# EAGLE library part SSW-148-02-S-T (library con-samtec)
THROUGH-HOLE .025" SQ POST SOCKET Source: Samtec SSW.pdf
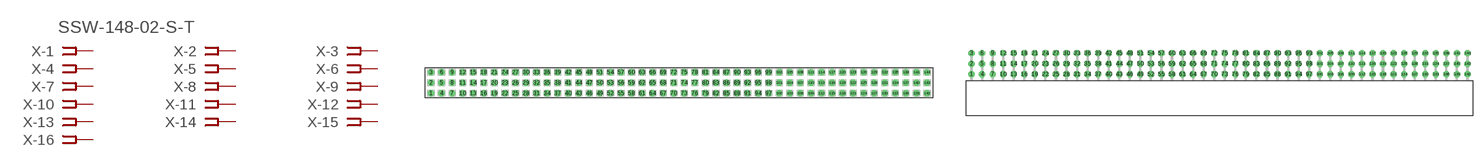
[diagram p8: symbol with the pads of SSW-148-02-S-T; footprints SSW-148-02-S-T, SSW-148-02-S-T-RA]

Designator prefix X; gates -1=FPINV -2=FPIN -3=FPIN -4=FPIN -5=FPIN -6=FPIN -7=FPIN -8=FPIN -9=FPIN -10=FPIN -11=FPIN -12=FPIN -13=FPIN -14=FPIN -15=FPIN -16=FPIN -17=FPIN -18=FPIN -19=FPIN -20=FPIN -21=FPIN -22=FPIN -23=FPIN -24=FPIN -25=FPIN -26=FPIN -27=FPIN -28=FPIN -29=FPIN -30=FPIN -31=FPIN -32=FPIN -33=FPIN -34=FPIN -35=FPIN -36=FPIN -37=FPIN -38=FPIN -39=FPIN -40=FPIN -41=FPIN -42=FPIN -43=FPIN -44=FPIN -45=FPIN -46=FPIN -47=FPIN -48=FPIN -49=FPIN -50=FPIN -51=FPIN -52=FPIN -53=FPIN -54=FPIN -55=FPIN -56=FPIN -57=FPIN -58=FPIN -59=FPIN -60=FPIN -61=FPIN -62=FPIN -63=FPIN -64=FPIN -65=FPIN -66=FPIN -67=FPIN -68=FPIN -69=FPIN -70=FPIN -71=FPIN -72=FPIN -73=FPIN -74=FPIN -75=FPIN -76=FPIN -77=FPIN -78=FPIN -79=FPIN -80=FPIN -81=FPIN -82=FPIN -83=FPIN -84=FPIN -85=FPIN -86=FPIN -87=FPIN -88=FPIN -89=FPIN -90=FPIN -91=FPIN -92=FPIN -93=FPIN -94=FPIN -95=FPIN -96=FPIN -97=FPIN -98=FPIN -99=FPIN -100=FPIN -101=FPIN -102=FPIN -103=FPIN -104=FPIN -105=FPIN -106=FPIN -107=FPIN -108=FPIN -109=FPIN -110=FPIN -111=FPIN -112=FPIN -113=FPIN -114=FPIN -115=FPIN -116=FPIN -117=FPIN -118=FPIN -119=FPIN -120=FPIN -121=FPIN -122=FPIN -123=FPIN -124=FPIN -125=FPIN -126=FPIN -127=FPIN -128=FPIN -129=FPIN -130=FPIN -131=FPIN -132=FPIN -133=FPIN -134=FPIN -135=FPIN -136=FPIN -137=FPIN -138=FPIN -139=FPIN -140=FPIN -141=FPIN -142=FPIN -143=FPIN -144=FPIN

## SSW-148-02-S-T (OC_FARNELL: unknown; OC_NEWARK: unknown)  [SSW-148-02-S-T]
1  -1:1  pas
2  -2:1  pas
3  -3:1  pas
4  -4:1  pas
5  -5:1  pas
6  -6:1  pas
7  -7:1  pas
8  -8:1  pas
9  -9:1  pas
10  -10:1  pas
11  -11:1  pas
12  -12:1  pas
13  -13:1  pas
14  -14:1  pas
15  -15:1  pas
16  -16:1  pas
17  -17:1  pas
18  -18:1  pas
19  -19:1  pas
20  -20:1  pas
21  -21:1  pas
22  -22:1  pas
23  -23:1  pas
24  -24:1  pas
25  -25:1  pas
26  -26:1  pas
27  -27:1  pas
28  -28:1  pas
29  -29:1  pas
30  -30:1  pas
31  -31:1  pas
32  -32:1  pas
33  -33:1  pas
34  -34:1  pas
35  -35:1  pas
36  -36:1  pas
37  -37:1  pas
38  -38:1  pas
39  -39:1  pas
40  -40:1  pas
41  -41:1  pas
42  -42:1  pas
43  -43:1  pas
44  -44:1  pas
45  -45:1  pas
46  -46:1  pas
47  -47:1  pas
48  -48:1  pas
49  -49:1  pas
50  -50:1  pas
51  -51:1  pas
52  -52:1  pas
53  -53:1  pas
54  -54:1  pas
55  -55:1  pas
56  -56:1  pas
57  -57:1  pas
58  -58:1  pas
59  -59:1  pas
60  -60:1  pas
61  -61:1  pas
62  -62:1  pas
63  -63:1  pas
64  -64:1  pas
65  -65:1  pas
66  -66:1  pas
67  -67:1  pas
68  -68:1  pas
69  -69:1  pas
70  -70:1  pas
71  -71:1  pas
72  -72:1  pas
73  -73:1  pas
74  -74:1  pas
75  -75:1  pas
76  -76:1  pas
77  -77:1  pas
78  -78:1  pas
79  -79:1  pas
80  -80:1  pas
81  -81:1  pas
82  -82:1  pas
83  -83:1  pas
84  -84:1  pas
85  -85:1  pas
86  -86:1  pas
87  -87:1  pas
88  -88:1  pas
89  -89:1  pas
90  -90:1  pas
91  -91:1  pas
92  -92:1  pas
93  -93:1  pas
94  -94:1  pas
95  -95:1  pas
96  -96:1  pas
97  -97:1  pas
98  -98:1  pas
99  -99:1  pas
100  -100:1  pas
101  -101:1  pas
102  -102:1  pas
103  -103:1  pas
104  -104:1  pas
105  -105:1  pas
106  -106:1  pas
107  -107:1  pas
108  -108:1  pas
109  -109:1  pas
110  -110:1  pas
111  -111:1  pas
112  -112:1  pas
113  -113:1  pas
114  -114:1  pas
115  -115:1  pas
116  -116:1  pas
117  -117:1  pas
118  -118:1  pas
119  -119:1  pas
120  -120:1  pas
121  -121:1  pas
122  -122:1  pas
123  -123:1  pas
124  -124:1  pas
125  -125:1  pas
126  -126:1  pas
127  -127:1  pas
128  -128:1  pas
129  -129:1  pas
130  -130:1  pas
131  -131:1  pas
132  -132:1  pas
133  -133:1  pas
134  -134:1  pas
135  -135:1  pas
136  -136:1  pas
137  -137:1  pas
138  -138:1  pas
139  -139:1  pas
140  -140:1  pas
141  -141:1  pas
142  -142:1  pas
143  -143:1  pas
144  -144:1  pas

## SSW-148-02-S-TRA (OC_FARNELL: unknown; OC_NEWARK: unknown)  [SSW-148-02-S-T-RA]
Pads as for SSW-148-02-S-T

## Footprint SSW-148-02-S-T (pad centres in mm)
THROUGH-HOLE .025" SQ POST SOCKET Source: Samtec SSW.pdf
drill 1 pad 1.5 octagon: 1 -59.69,-2.54; 2 -59.69,0; 3 -59.69,2.54; 4 -57.15,-2.54; 5 -57.15,0; 6 -57.15,2.54; 7 -54.61,-2.54; 8 -54.61,0; 9 -54.61,2.54; 10 -52.07,-2.54; 11 -52.07,0; 12 -52.07,2.54; 13 -49.53,-2.54; 14 -49.53,0; 15 -49.53,2.54; 16 -46.99,-2.54; 17 -46.99,0; 18 -46.99,2.54; 19 -44.45,-2.54; 20 -44.45,0; 21 -44.45,2.54; 22 -41.91,-2.54; 23 -41.91,0; 24 -41.91,2.54; 25 -39.37,-2.54; 26 -39.37,0; 27 -39.37,2.54; 28 -36.83,-2.54; 29 -36.83,0; 30 -36.83,2.54; 31 -34.29,-2.54; 32 -34.29,0; 33 -34.29,2.54; 34 -31.75,-2.54; 35 -31.75,0; 36 -31.75,2.54; 37 -29.21,-2.54; 38 -29.21,0; 39 -29.21,2.54; 40 -26.67,-2.54; 41 -26.67,0; 42 -26.67,2.54; 43 -24.13,-2.54; 44 -24.13,0; 45 -24.13,2.54; 46 -21.59,-2.54; 47 -21.59,0; 48 -21.59,2.54; 49 -19.05,-2.54; 50 -19.05,0; 51 -19.05,2.54; 52 -16.51,-2.54; 53 -16.51,0; 54 -16.51,2.54; 55 -13.97,-2.54; 56 -13.97,0; 57 -13.97,2.54; 58 -11.43,-2.54; 59 -11.43,0; 60 -11.43,2.54; 61 -8.89,-2.54; 62 -8.89,0; 63 -8.89,2.54; 64 -6.35,-2.54; 65 -6.35,0; 66 -6.35,2.54; 67 -3.81,-2.54; 68 -3.81,0; 69 -3.81,2.54; 70 -1.27,-2.54; 71 -1.27,0; 72 -1.27,2.54; 73 1.27,-2.54; 74 1.27,0; 75 1.27,2.54; 76 3.81,-2.54; 77 3.81,0; 78 3.81,2.54; 79 6.35,-2.54; 80 6.35,0; 81 6.35,2.54; 82 8.89,-2.54; 83 8.89,0; 84 8.89,2.54; 85 11.43,-2.54; 86 11.43,0; 87 11.43,2.54; 88 13.97,-2.54; 89 13.97,0; 90 13.97,2.54; 91 16.51,-2.54; 92 16.51,0; 93 16.51,2.54; 94 19.05,-2.54; 95 19.05,0; 96 19.05,2.54; 97 21.59,-2.54; 98 21.59,0; 99 21.59,2.54; 100 24.13,-2.54; 101 24.13,0; 102 24.13,2.54; 103 26.67,-2.54; 104 26.67,0; 105 26.67,2.54; 106 29.21,-2.54; 107 29.21,0; 108 29.21,2.54; 109 31.75,-2.54; 110 31.75,0; 111 31.75,2.54; 112 34.29,-2.54; 113 34.29,0; 114 34.29,2.54; 115 36.83,-2.54; 116 36.83,0; 117 36.83,2.54; 118 39.37,-2.54; 119 39.37,0; 120 39.37,2.54; 121 41.91,-2.54; 122 41.91,0; 123 41.91,2.54; 124 44.45,-2.54; 125 44.45,0; 126 44.45,2.54; 127 46.99,-2.54; 128 46.99,0; 129 46.99,2.54; 130 49.53,-2.54; 131 49.53,0; 132 49.53,2.54; 133 52.07,-2.54; 134 52.07,0; 135 52.07,2.54; 136 54.61,-2.54; 137 54.61,0; 138 54.61,2.54; 139 57.15,-2.54; 140 57.15,0; 141 57.15,2.54; 142 59.69,-2.54; 143 59.69,0; 144 59.69,2.54

## Footprint SSW-148-02-S-T-RA (pad centres in mm)
THROUGH-HOLE .025" SQ POST SOCKET Source: Samtec SSW.pdf
drill 1 pad 1.5 octagon: 1 -59.69,1.524; 2 -59.69,4.064; 3 -59.69,6.604; 4 -57.15,1.524; 5 -57.15,4.064; 6 -57.15,6.604; 7 -54.61,1.524; 8 -54.61,4.064; 9 -54.61,6.604; 10 -52.07,1.524; 11 -52.07,4.064; 12 -52.07,6.604; 13 -49.53,1.524; 14 -49.53,4.064; 15 -49.53,6.604; 16 -46.99,1.524; 17 -46.99,4.064; 18 -46.99,6.604; 19 -44.45,1.524; 20 -44.45,4.064; 21 -44.45,6.604; 22 -41.91,1.524; 23 -41.91,4.064; 24 -41.91,6.604; 25 -39.37,1.524; 26 -39.37,4.064; 27 -39.37,6.604; 28 -36.83,1.524; 29 -36.83,4.064; 30 -36.83,6.604; 31 -34.29,1.524; 32 -34.29,4.064; 33 -34.29,6.604; 34 -31.75,1.524; 35 -31.75,4.064; 36 -31.75,6.604; 37 -29.21,1.524; 38 -29.21,4.064; 39 -29.21,6.604; 40 -26.67,1.524; 41 -26.67,4.064; 42 -26.67,6.604; 43 -24.13,1.524; 44 -24.13,4.064; 45 -24.13,6.604; 46 -21.59,1.524; 47 -21.59,4.064; 48 -21.59,6.604; 49 -19.05,1.524; 50 -19.05,4.064; 51 -19.05,6.604; 52 -16.51,1.524; 53 -16.51,4.064; 54 -16.51,6.604; 55 -13.97,1.524; 56 -13.97,4.064; 57 -13.97,6.604; 58 -11.43,1.524; 59 -11.43,4.064; 60 -11.43,6.604; 61 -8.89,1.524; 62 -8.89,4.064; 63 -8.89,6.604; 64 -6.35,1.524; 65 -6.35,4.064; 66 -6.35,6.604; 67 -3.81,1.524; 68 -3.81,4.064; 69 -3.81,6.604; 70 -1.27,1.524; 71 -1.27,4.064; 72 -1.27,6.604; 73 1.27,1.524; 74 1.27,4.064; 75 1.27,6.604; 76 3.81,1.524; 77 3.81,4.064; 78 3.81,6.604; 79 6.35,1.524; 80 6.35,4.064; 81 6.35,6.604; 82 8.89,1.524; 83 8.89,4.064; 84 8.89,6.604; 85 11.43,1.524; 86 11.43,4.064; 87 11.43,6.604; 88 13.97,1.524; 89 13.97,4.064; 90 13.97,6.604; 91 16.51,1.524; 92 16.51,4.064; 93 16.51,6.604; 94 19.05,1.524; 95 19.05,4.064; 96 19.05,6.604; 97 21.59,1.524; 98 21.59,4.064; 99 21.59,6.604; 100 24.13,1.524; 101 24.13,4.064; 102 24.13,6.604; 103 26.67,1.524; 104 26.67,4.064; 105 26.67,6.604; 106 29.21,1.524; 107 29.21,4.064; 108 29.21,6.604; 109 31.75,1.524; 110 31.75,4.064; 111 31.75,6.604; 112 34.29,1.524; 113 34.29,4.064; 114 34.29,6.604; 115 36.83,1.524; 116 36.83,4.064; 117 36.83,6.604; 118 39.37,1.524; 119 39.37,4.064; 120 39.37,6.604; 121 41.91,1.524; 122 41.91,4.064; 123 41.91,6.604; 124 44.45,1.524; 125 44.45,4.064; 126 44.45,6.604; 127 46.99,1.524; 128 46.99,4.064; 129 46.99,6.604; 130 49.53,1.524; 131 49.53,4.064; 132 49.53,6.604; 133 52.07,1.524; 134 52.07,4.064; 135 52.07,6.604; 136 54.61,1.524; 137 54.61,4.064; 138 54.61,6.604; 139 57.15,1.524; 140 57.15,4.064; 141 57.15,6.604; 142 59.69,1.524; 143 59.69,4.064; 144 59.69,6.604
